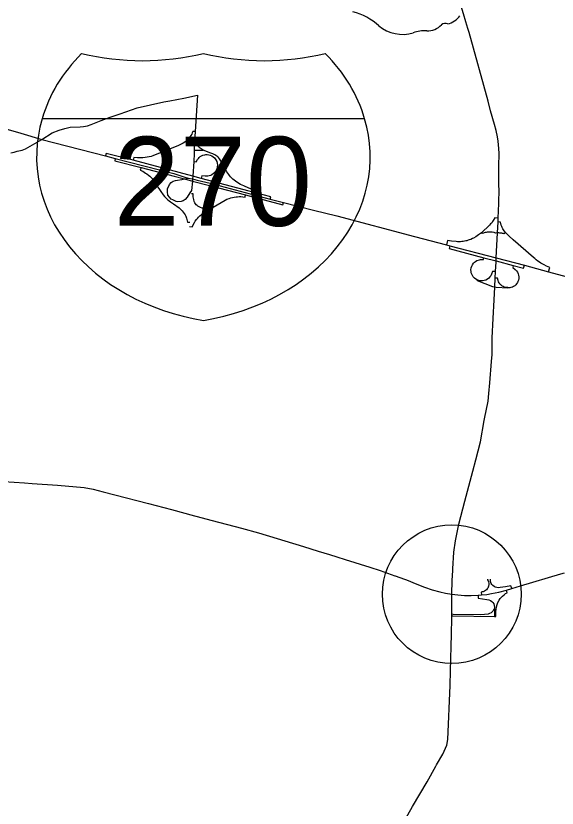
# Model space of a CAD drawing. Extents: x -7.1 to 34, y 0 to 22.
# Drawn here: x 6.165 to 6.728, y 18.876 to 19.7 of the extents above; entities that cross this region are included whole.
import ezdxf

# ---------------------------------------------------------------- set-up
doc = ezdxf.new("R2010")
doc.units = 0
for name, color, linetype in [('GM_X_Interchange_Ramps', 7, 'Continuous'), ('GM_X_Interstate_Route', 7, 'Continuous'), ('GM_X_Interstate_Shield', 7, 'Continuous'), ('GM_X_State_Route', 7, 'Continuous'), ('GM_X_State_Shield', 7, 'Continuous'), ('SH_Text', 7, 'Continuous')]:
    doc.layers.add(name, color=color, linetype=linetype)

msp = doc.modelspace()

# ---------------------------------------------------------------- linework, layer by layer
at = {"layer": 'GM_X_Interchange_Ramps'}
for points in [[(6.35126, 19.57967), (6.34895, 19.5798), (6.34834, 19.57832), (6.34772, 19.57704), (6.34691, 19.5756), (6.34613, 19.57441), (6.34506, 19.57298), (6.34385, 19.57159), (6.34231, 19.57008), (6.34063, 19.5687), (6.33901, 19.56759), (6.33693, 19.56642), (6.33406, 19.56519), (6.30745, 19.55446), (6.30559, 19.55387), (6.30356, 19.55334), (6.30126, 19.55285), (6.29939, 19.55256), (6.29707, 19.55231), (6.29545, 19.55221), (6.2934, 19.55217), (6.29129, 19.55224), (6.28746, 19.55256), (6.28675, 19.5499)], [(6.41413, 19.51588), (6.41477, 19.51842), (6.4073, 19.52088), (6.40189, 19.52307), (6.39837, 19.52467), (6.39458, 19.52699), (6.3932, 19.52797), (6.39196, 19.52897), (6.39053, 19.53023), (6.38914, 19.53161), (6.38821, 19.53263), (6.38711, 19.53395), (6.38624, 19.53509), (6.38524, 19.53654), (6.3844, 19.5379), (6.38369, 19.53917), (6.38309, 19.54037), (6.38259, 19.54145), (6.37877, 19.54821), (6.37821, 19.54918), (6.37746, 19.55031), (6.37668, 19.55132), (6.3756, 19.5525), (6.37481, 19.55325), (6.37389, 19.55402), (6.37285, 19.55478), (6.37197, 19.55534), (6.37099, 19.55589), (6.36985, 19.55643), (6.36883, 19.55684), (6.36764, 19.55723), (6.35977, 19.56042), (6.35858, 19.56099), (6.35766, 19.56154), (6.35673, 19.56223), (6.35588, 19.563), (6.35515, 19.5638), (6.35436, 19.56489), (6.35385, 19.56575), (6.35242, 19.56881), (6.35065, 19.5689)], [(6.35977, 19.56042), (6.35957, 19.55993), (6.35205, 19.56001), (6.35033, 19.56001)], [(6.42943, 19.50947), (6.42998, 19.51164), (6.41413, 19.51588), (6.35752, 19.531), (6.34888, 19.5333), (6.28675, 19.5499), (6.25867, 19.55668), (6.25803, 19.55428)], [(6.26824, 19.55164), (6.26761, 19.54926), (6.29502, 19.54211), (6.32956, 19.53311), (6.34019, 19.53034), (6.34848, 19.52817), (6.36621, 19.52353), (6.40385, 19.51369), (6.44259, 19.50356), (6.44319, 19.50593)], [(6.34992, 19.5484), (6.35249, 19.54822), (6.35395, 19.55057), (6.35467, 19.55156), (6.35569, 19.55272), (6.35664, 19.55364), (6.35792, 19.55445), (6.3595, 19.55514), (6.36129, 19.5556), (6.36255, 19.55575), (6.36381, 19.55575), (6.36572, 19.55548), (6.36708, 19.55508), (6.3687, 19.55434), (6.37003, 19.55348), (6.37145, 19.5522), (6.37282, 19.55041), (6.37376, 19.54851), (6.37424, 19.54692), (6.37449, 19.54501), (6.37439, 19.54285), (6.37395, 19.54097), (6.37322, 19.53924), (6.37232, 19.5378), (6.37147, 19.53676), (6.37015, 19.53556), (6.3688, 19.53466), (6.36763, 19.53408), (6.36606, 19.53354), (6.36458, 19.53326), (6.36187, 19.53322), (6.35823, 19.53346), (6.35752, 19.531)], [(6.29502, 19.54211), (6.2943, 19.53936), (6.29674, 19.53833), (6.29832, 19.53745), (6.2998, 19.53653), (6.30124, 19.53552), (6.30264, 19.53445), (6.30417, 19.53312), (6.30544, 19.53191), (6.30681, 19.53044), (6.30811, 19.52888), (6.30894, 19.52778), (6.30991, 19.52637), (6.31067, 19.52515), (6.31129, 19.52407), (6.31566, 19.51746), (6.31645, 19.51617), (6.31733, 19.51486), (6.31813, 19.51376), (6.31933, 19.51228), (6.32049, 19.51099), (6.3216, 19.50988), (6.32295, 19.50864), (6.32417, 19.50764), (6.32564, 19.50654), (6.32685, 19.50573), (6.32866, 19.50465), (6.33469, 19.50018), (6.33588, 19.4992), (6.33694, 19.49821), (6.33793, 19.49716), (6.33896, 19.49591), (6.33996, 19.49449), (6.34083, 19.49303), (6.34159, 19.49152), (6.34201, 19.49051), (6.3424, 19.48944), (6.34279, 19.48816), (6.3434, 19.48557), (6.34572, 19.48544)], [(6.36621, 19.52353), (6.36548, 19.52102), (6.36671, 19.52006), (6.36757, 19.51929), (6.36877, 19.51803), (6.36977, 19.51668), (6.3704, 19.51553), (6.37099, 19.51396), (6.37135, 19.51228), (6.37142, 19.51024), (6.37115, 19.50839), (6.37054, 19.50655), (6.36991, 19.50531), (6.36921, 19.50427), (6.36821, 19.50312), (6.36721, 19.50224), (6.36626, 19.50159), (6.36495, 19.50089), (6.36365, 19.50041), (6.36229, 19.50009), (6.36025, 19.49995), (6.3586, 19.50011), (6.35703, 19.50051), (6.35543, 19.5012), (6.35423, 19.50193), (6.35332, 19.50263), (6.35251, 19.50343), (6.3517, 19.50439), (6.35099, 19.50549), (6.35031, 19.50696), (6.34983, 19.50888), (6.34956, 19.51033), (6.34935, 19.51189), (6.34913, 19.51489), (6.3474, 19.51498)], [(6.34546, 19.48081), (6.34826, 19.48065), (6.3506, 19.48504), (6.35153, 19.48653), (6.35261, 19.48804), (6.35368, 19.48939), (6.35489, 19.49073), (6.35624, 19.49205), (6.35781, 19.49339), (6.35944, 19.49461), (6.36173, 19.49605), (6.38253, 19.50835), (6.38446, 19.50926), (6.3867, 19.51013), (6.38834, 19.51065), (6.39012, 19.51112), (6.39196, 19.51149), (6.39385, 19.51177), (6.39557, 19.51192), (6.39715, 19.51199), (6.39887, 19.51197), (6.40098, 19.51184), (6.4033, 19.51153), (6.40385, 19.51369)], [(6.66667, 19.48973), (6.66315, 19.4899), (6.66157, 19.48717), (6.66078, 19.48598), (6.66021, 19.4852), (6.65952, 19.48435), (6.6588, 19.48354), (6.65774, 19.48246), (6.64917, 19.4745), (6.64602, 19.47214), (6.64334, 19.47024), (6.64109, 19.46896), (6.64005, 19.46842), (6.63821, 19.46757), (6.63658, 19.46693), (6.63553, 19.46658), (6.63417, 19.46617), (6.63285, 19.46585), (6.63141, 19.46556), (6.63019, 19.46537), (6.62873, 19.46521), (6.62733, 19.46512), (6.62589, 19.46509), (6.62429, 19.46513), (6.62288, 19.46524), (6.61807, 19.4657), (6.61392, 19.4665), (6.6127, 19.46182)], [(6.71909, 19.43371), (6.7203, 19.43825), (6.71701, 19.4396), (6.71436, 19.44091), (6.71242, 19.44195), (6.71088, 19.44288), (6.70946, 19.44381), (6.70778, 19.44502), (6.70626, 19.44623), (6.70474, 19.44755), (6.70352, 19.4487), (6.68206, 19.46705), (6.67793, 19.47079), (6.67413, 19.47454), (6.67278, 19.47637), (6.67202, 19.47755), (6.67148, 19.47851), (6.67086, 19.47975), (6.67034, 19.48094), (6.66979, 19.48247), (6.66891, 19.48552), (6.66645, 19.48564)], [(6.66584, 19.47418), (6.66396, 19.47414), (6.66231, 19.47458), (6.66027, 19.47487), (6.65789, 19.47497), (6.65528, 19.47488), (6.654, 19.47471), (6.65315, 19.47459), (6.65221, 19.47441), (6.65119, 19.47413), (6.64986, 19.47369), (6.64917, 19.4745)], [(6.67413, 19.47454), (6.67298, 19.47322), (6.67211, 19.47354), (6.67119, 19.47379), (6.67032, 19.47396), (6.66925, 19.47409), (6.66829, 19.47413), (6.6674, 19.47419), (6.66584, 19.47418)], [(6.61631, 19.46088), (6.61557, 19.45809), (6.65181, 19.44851), (6.66444, 19.44517), (6.68235, 19.44044), (6.69313, 19.43759), (6.69392, 19.44058)], [(6.66395, 19.43401), (6.66078, 19.4341), (6.65968, 19.43119), (6.65891, 19.42968), (6.65802, 19.42841), (6.65692, 19.42725), (6.65549, 19.42614), (6.65372, 19.4252), (6.65213, 19.42467), (6.65061, 19.4244), (6.64834, 19.42439), (6.64656, 19.42471), (6.64522, 19.42513), (6.64334, 19.42615), (6.64194, 19.42723), (6.64076, 19.42849), (6.63974, 19.43), (6.63914, 19.43123), (6.63867, 19.43263), (6.63838, 19.43414), (6.63832, 19.43597), (6.63861, 19.43802), (6.63909, 19.43955), (6.63979, 19.441), (6.64105, 19.44277), (6.64212, 19.44383), (6.64308, 19.44458), (6.64448, 19.4454), (6.64597, 19.44601), (6.64722, 19.44634), (6.64816, 19.44649), (6.64945, 19.44659), (6.65133, 19.44662), (6.65181, 19.44851)], [(6.68235, 19.44044), (6.68177, 19.43827), (6.68427, 19.43634), (6.68558, 19.43496), (6.68656, 19.43352), (6.68735, 19.43181), (6.6878, 19.4302), (6.688, 19.4286), (6.68795, 19.42685), (6.68764, 19.42523), (6.68715, 19.42378), (6.68655, 19.42256), (6.68579, 19.42142), (6.68482, 19.4203), (6.68378, 19.41937), (6.68272, 19.41863), (6.68136, 19.41793), (6.67985, 19.41751), (6.6788, 19.41731), (6.67782, 19.41727), (6.67661, 19.41733), (6.67448, 19.41755), (6.67282, 19.41799), (6.67177, 19.41845), (6.67049, 19.41914), (6.66922, 19.42023), (6.66844, 19.42109), (6.66758, 19.4223), (6.66702, 19.42335), (6.66648, 19.42471), (6.66591, 19.42711), (6.66365, 19.42717)], [(6.66323, 19.41769), (6.66095, 19.41829), (6.645, 19.42445), (6.64522, 19.42513)], [(6.67661, 19.41733), (6.67656, 19.41685), (6.66443, 19.41764), (6.66323, 19.41769)], [(6.65546, 19.11419), (6.65549, 19.11335), (6.6563, 19.1124), (6.65672, 19.11135), (6.65693, 19.11016), (6.65689, 19.10862), (6.65668, 19.10704), (6.65626, 19.10585), (6.65574, 19.10483), (6.65514, 19.10413), (6.65433, 19.10326), (6.65339, 19.10256), (6.65223, 19.10175), (6.65101, 19.10119), (6.65002, 19.10087), (6.64906, 19.10073), (6.64918, 19.09787)], [(6.68074, 19.10442), (6.67992, 19.10728), (6.67411, 19.10618), (6.66866, 19.10537), (6.66702, 19.10529), (6.66537, 19.10543), (6.66337, 19.10585), (6.66232, 19.10652), (6.66096, 19.1075), (6.65991, 19.10872), (6.65942, 19.10971), (6.65871, 19.11174), (6.65868, 19.11321), (6.65862, 19.11434)], [(6.61829, 19.07598), (6.6195, 19.07598), (6.66264, 19.0754), (6.66432, 19.07544), (6.66428, 19.08026), (6.66439, 19.08302), (6.66474, 19.08538), (6.66549, 19.0878), (6.66637, 19.09001), (6.6677, 19.09244), (6.6688, 19.09395), (6.66973, 19.09517), (6.67109, 19.09653), (6.67271, 19.09792), (6.67422, 19.09915), (6.67591, 19.10007), (6.67512, 19.10284)], [(6.64578, 19.09754), (6.64587, 19.09451), (6.6547, 19.09318), (6.65691, 19.09266), (6.65857, 19.09196), (6.66, 19.09108), (6.66115, 19.08987), (6.66196, 19.08858), (6.66254, 19.08685), (6.66266, 19.08486), (6.66229, 19.08305), (6.66184, 19.08221), (6.66122, 19.08107), (6.66041, 19.08007), (6.65934, 19.07919), (6.65776, 19.07834), (6.65628, 19.07786), (6.65253, 19.07731), (6.64778, 19.07709), (6.61971, 19.07762), (6.61829, 19.07764)], [(6.66229, 19.08305), (6.66284, 19.08298), (6.66275, 19.07677), (6.66264, 19.0754)]]:
    msp.add_lwpolyline(points, dxfattribs=at)
at = {"layer": 'GM_X_Interstate_Route'}
for points in [[(6.07143, 19.60381), (6.07803, 19.60227), (6.11912, 19.59143), (6.15665, 19.58173), (6.17006, 19.5778)], [(6.17006, 19.5778), (6.19176, 19.57146)], [(6.19176, 19.57146), (6.25803, 19.55428)], [(6.25803, 19.55428), (6.26824, 19.55164)], [(6.26824, 19.55164), (6.32912, 19.53588), (6.33944, 19.53265)], [(6.33944, 19.53265), (6.34413, 19.53118), (6.34868, 19.53041)], [(6.34868, 19.53041), (6.35331, 19.52927)], [(6.35331, 19.52927), (6.36691, 19.52593), (6.42943, 19.50947)], [(6.42943, 19.50947), (6.44319, 19.50593)], [(6.44319, 19.50593), (6.47438, 19.4979), (6.49872, 19.49206), (6.57962, 19.47052), (6.6127, 19.46182), (6.61631, 19.46088)], [(6.61631, 19.46088), (6.66458, 19.44832)], [(6.66458, 19.44832), (6.69392, 19.44058)], [(6.69392, 19.44058), (6.71909, 19.43371)], [(6.71909, 19.43371), (6.71909, 19.43371), (6.74375, 19.42716), (6.75404, 19.42424), (6.765, 19.41983), (6.7722, 19.41694), (6.78325, 19.41142), (6.79382, 19.40541), (6.81462, 19.3909)]]:
    msp.add_lwpolyline(points, dxfattribs=at)
at = {"layer": 'GM_X_Interstate_Shield'}
msp.add_line((6.52771, 19.59296), (6.19212, 19.59296), dxfattribs=at)
msp.add_line((6.52771, 19.59296), (6.19212, 19.59296), dxfattribs=at)
for centre, start_param, end_param in [((6.4033, 19.55331), 2.47259, 2.911027), ((6.29652, 19.82689), 4.415841, 5.008937), ((6.4233, 19.82689), 4.415841, 5.008937), ((6.31653, 19.55331), 0.230566, 0.669003), ((6.4033, 19.55331), 2.911027, 4.511031), ((6.31653, 19.55331), 4.913747, 6.513751)]:
    msp.add_ellipse(centre, major_axis=(0.21692, 0), ratio=0.8, start_param=start_param, end_param=end_param, dxfattribs=at)
at = {"layer": 'GM_X_State_Route'}
for points in [[(6.63511, 19.68666), (6.63296, 19.69385), (6.63059, 19.70193), (6.62567, 19.7184), (6.62538, 19.71949)], [(6.66754, 19.55474), (6.66756, 19.55682), (6.6674, 19.56189), (6.66658, 19.56976), (6.66592, 19.5741), (6.66437, 19.58073), (6.66273, 19.58688), (6.65874, 19.60125), (6.6561, 19.61129), (6.63636, 19.68248), (6.63511, 19.68666)], [(6.1595, 19.55754), (6.16295, 19.55807), (6.16612, 19.55926), (6.17141, 19.56032), (6.17484, 19.56177), (6.19176, 19.57146), (6.2027, 19.57815), (6.2097, 19.58119), (6.21578, 19.58291), (6.22119, 19.58423), (6.23176, 19.58463), (6.23532, 19.58502), (6.23928, 19.58568), (6.24311, 19.58713), (6.25355, 19.5911), (6.26305, 19.59449), (6.27343, 19.5982), (6.2911, 19.60435), (6.31893, 19.61048), (6.32496, 19.61166), (6.33953, 19.61449), (6.35388, 19.61751)], [(6.35388, 19.61751), (6.35126, 19.57967), (6.35065, 19.5689), (6.35033, 19.56001), (6.35022, 19.55669)], [(6.35022, 19.55669), (6.34992, 19.5484), (6.34888, 19.5333), (6.34868, 19.53041), (6.34848, 19.52817), (6.3476, 19.51847)], [(6.66739, 19.52723), (6.66728, 19.53205), (6.66747, 19.54557), (6.66754, 19.55474)], [(6.3476, 19.51847), (6.34578, 19.5159), (6.34313, 19.51142), (6.34097, 19.50902), (6.33899, 19.50778), (6.33683, 19.50695), (6.33318, 19.50653), (6.33144, 19.50678), (6.32805, 19.50852), (6.32656, 19.50935), (6.32457, 19.51126), (6.32308, 19.51366), (6.32241, 19.51698), (6.32274, 19.52054), (6.32382, 19.52303), (6.32482, 19.52452), (6.32639, 19.52659), (6.32863, 19.52808), (6.33086, 19.52891), (6.3331, 19.52924), (6.33741, 19.52974), (6.34019, 19.53034), (6.34413, 19.53118)], [(6.66746, 19.50972), (6.66768, 19.51514), (6.66739, 19.52723)], [(6.66726, 19.50472), (6.66746, 19.50972)], [(6.6644, 19.44423), (6.66444, 19.44517), (6.66458, 19.44832), (6.66584, 19.47418), (6.66645, 19.48564), (6.66667, 19.48973), (6.66726, 19.50472)], [(6.66149, 19.3851), (6.66242, 19.40461), (6.66323, 19.41769), (6.66365, 19.42717), (6.66395, 19.43401), (6.6644, 19.44423)], [(6.65239, 19.28092), (6.6563, 19.29915), (6.65698, 19.30713), (6.65792, 19.31832), (6.65956, 19.34063), (6.66032, 19.34796), (6.66053, 19.36504), (6.66149, 19.3851)], [(6.64576, 19.24771), (6.64809, 19.25696), (6.65202, 19.2792), (6.65239, 19.28092)], [(6.64021, 19.22645), (6.64339, 19.23832), (6.64576, 19.24771)], [(5.89097, 19.23053), (5.89563, 19.23027), (5.92189, 19.22931), (5.93844, 19.22847), (5.99642, 19.22519), (6.01361, 19.22407), (6.06659, 19.22078), (6.08784, 19.21969), (6.13998, 19.2166), (6.15219, 19.21572), (6.17365, 19.21432)], [(6.61928, 19.12311), (6.61937, 19.12493), (6.62059, 19.14229), (6.62237, 19.15401), (6.6257, 19.17155), (6.6319, 19.19544), (6.64021, 19.22645)], [(6.17365, 19.21432), (6.18163, 19.21379), (6.20811, 19.21198), (6.2358, 19.2095), (6.24516, 19.20796), (6.25567, 19.20512), (6.26776, 19.20182), (6.30278, 19.19295), (6.32678, 19.18657), (6.35073, 19.18017)], [(6.35073, 19.18017), (6.35219, 19.17978), (6.36894, 19.17534), (6.39968, 19.16733), (6.41738, 19.16253), (6.46412, 19.14818), (6.47939, 19.14344)], [(6.47939, 19.14344), (6.49122, 19.13976)], [(6.49122, 19.13976), (6.4989, 19.13738), (6.50756, 19.13469), (6.53316, 19.1267), (6.54375, 19.12312), (6.54393, 19.12306), (6.55922, 19.11773), (6.55958, 19.1176)], [(6.61834, 19.09593), (6.61835, 19.09854), (6.61876, 19.11289), (6.61928, 19.12311)], [(6.55958, 19.1176), (6.56925, 19.11423), (6.57124, 19.1134)], [(6.6899, 19.10716), (6.73173, 19.11966), (6.73567, 19.12085)], [(6.57124, 19.1134), (6.58186, 19.10896), (6.59013, 19.10576), (6.59796, 19.10309), (6.60591, 19.10092), (6.61186, 19.09964), (6.61835, 19.09854)], [(6.61835, 19.09854), (6.62451, 19.09782), (6.63166, 19.09734), (6.63868, 19.0973), (6.64578, 19.09754), (6.64918, 19.09787), (6.65476, 19.09841), (6.65965, 19.09919), (6.6673, 19.10078), (6.67512, 19.10284), (6.68074, 19.10442), (6.6899, 19.10716)], [(6.61825, 19.07361), (6.61829, 19.07598), (6.61829, 19.07764), (6.61829, 19.08659), (6.61834, 19.09593)], [(6.618, 19.057), (6.61825, 19.07361)], [(6.61651, 19.00348), (6.61709, 19.01883), (6.618, 19.057)], [(6.60258, 18.92111), (6.60889, 18.93236), (6.61331, 18.94143), (6.61437, 18.94736), (6.61651, 19.00348)], [(6.51744, 18.77359), (6.51921, 18.77665), (6.52054, 18.77889), (6.533, 18.79993), (6.53356, 18.80087), (6.53505, 18.80347), (6.54317, 18.81759), (6.55401, 18.83647), (6.56621, 18.85788), (6.5664, 18.8582), (6.57738, 18.8779), (6.59266, 18.90342), (6.60178, 18.91968), (6.60258, 18.92111)]]:
    msp.add_lwpolyline(points, dxfattribs=at)
at = {"layer": 'GM_X_State_Shield'}
for centre, radius, start, end in [((6.50046, 19.64426), 0.06175, 47.18416, 75.83597), ((6.60912, 19.71317), 0.02208, 282.87319, 323.27711), ((6.59274, 19.70522), 0.02088, 268.77702, 315.54927), ((6.61163, 19.68628), 0.00588, 65.75173, 132.64842), ((6.56724, 19.71987), 0.03918, 230.70037, 286.29184), ((6.58988, 19.65225), 0.03219, 85.69512, 111.20995)]:
    msp.add_arc(centre, radius, start, end, dxfattribs=at)
at = {"layer": 'SH_Text'}
msp.add_circle((6.61835, 19.09854), 0.07217, dxfattribs=at)

# ---------------------------------------------------------------- texts
at = {"layer": 'GM_X_Interstate_Shield'}
msp.add_text('270', height=0.092551, dxfattribs=at).set_placement((6.26644, 19.48162))

doc.saveas('drawing.dxf')
